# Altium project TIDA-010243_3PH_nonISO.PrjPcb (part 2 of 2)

## Sheet TIDA-010243_Hardware.SchDoc
size 431 x 279 mm; Date: Not shown in title block; ApprovedBy: Not shown in title block; CheckedBy: Not shown in title block; Author: Not shown in title block; CompanyName: Not shown in title block; Engineer: Not shown in title block; Organization: Not shown in title block; Address1: Not shown in title block; Address2: Not shown in title block; Address3: Not shown in title block; Address4: Not shown in title block; DocumentNumber: 3; Revision: Use project parameter SCH_Rev; SheetNumber: 4; SheetTotal: 4; PageSetup: Record=PageOptions¦CenterHorizontal=True¦CenterVertical=True¦PrintScale=1.00¦XCorrection=1.00¦YCorrection=1.00¦PrintKind=0¦BorderSize=5000000¦LeftOffset=0¦BottomOffset=0¦Orientation=2¦PaperLength=1000¦PaperWidth=1000¦Scale=100¦PaperSource=15¦PrintQuality=600¦MediaType=1¦DitherType=10¦PaperKind=Letter¦PrintScaleMode=1
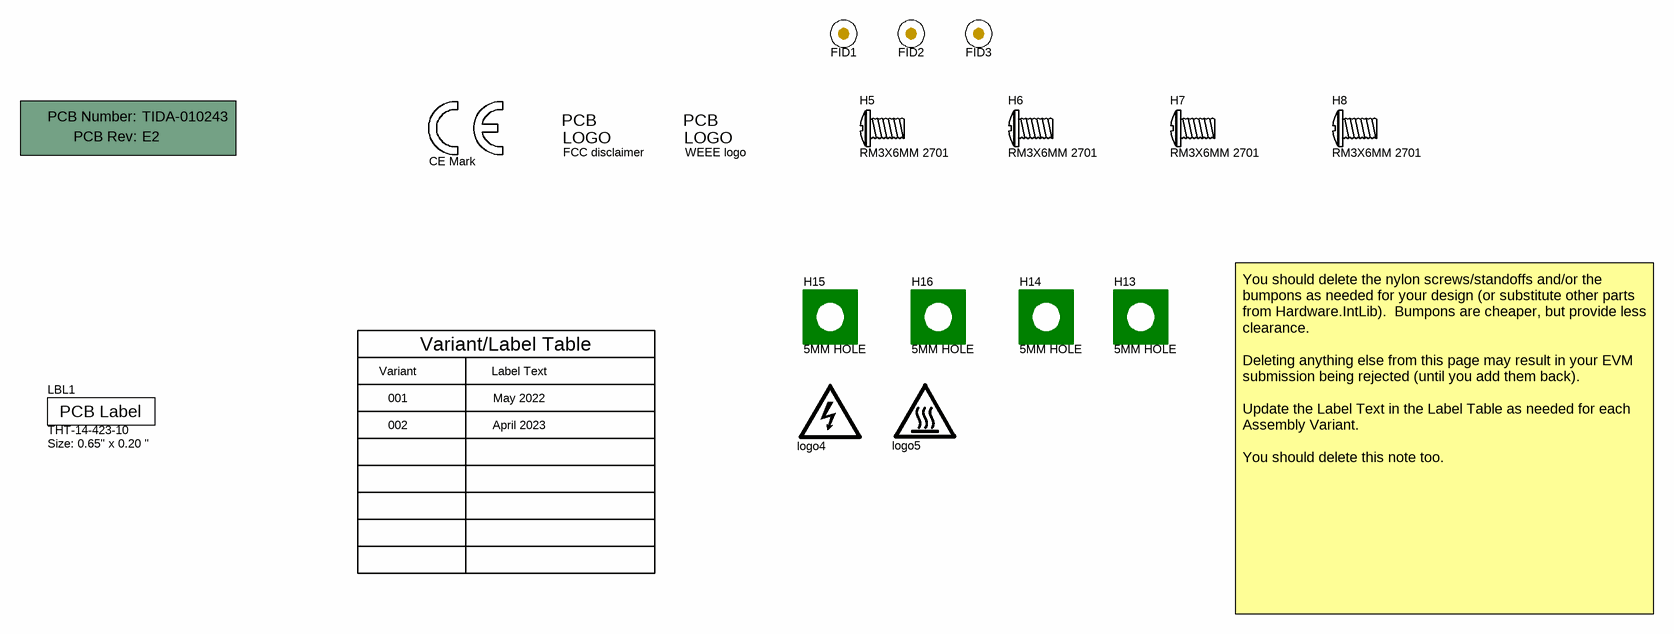
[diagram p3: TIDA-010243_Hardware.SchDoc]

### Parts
(Parts that share a designator on the sheet are numbered #1, #2 ... from top to bottom, then left to right.)
!PCB  Printed Circuit Board  (value not drawn)  (mechanical)
FID1  Fiducial  [Fiducial10-30]  (value not drawn)
FID2  Fiducial  [Fiducial10-30]  (value not drawn)
FID3  Fiducial  [Fiducial10-30]  (value not drawn)
H5  RM3X6MM 2701  (mechanical)
H6  RM3X6MM 2701  (mechanical)
H7  RM3X6MM 2701  (mechanical)
H8  RM3X6MM 2701  (mechanical)
H13  5MM HOLE  [5MM_HOLE]
H14  5MM HOLE  [5MM_HOLE]
H15  5MM HOLE  [5MM_HOLE]
H16  5MM HOLE  [5MM_HOLE]
LBL1  THT-14-423-10  Note: Size: 0.65" x 0.20 "  [Label_650x200]
Logo2  CE Mark  [CE_Mark_5mm]  (no BOM)
Logo3  FCC disclaimer  [FCC_disclaimer]  (no BOM)
Logo4#1  WEEE logo  [WEEE_Minimum]  (no BOM)
logo4#2  DANGER HIGH VOLTAGE  [IEC_HighVoltage_Large]  (value not drawn)  (no BOM)
logo5  CAUTION HOT SURFACE  [IEC_HotSurface_Large]  (value not drawn)  (no BOM)

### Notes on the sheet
- Variant
- Variant/Label Table
- Label Text
- 001
- 002
- May 2022
- April 2023
- You should delete the nylon screws/standoffs and/or the bumpons as needed for your design (or substitute other parts from Hardware.IntLib).  Bumpons are cheaper, but provide less clearance.
  Deleting anything else from this page may result in your EVM submission being rejected (until you add them back).
  Update the Label Text in the Label Table as needed for each Assembly Variant.
  You should delete this note too.

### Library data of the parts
!PCB = CMP-0003618-2: Manufacturer: Any; PartNumber: TIDA-010243
FID1-FID3 = CMP-0077181-1: Fiducial mark.  There is nothing to buy or mount.
H5-H8 = CMP-0077936-1: MACHINE SCREW PAN PHILLIPS M3; Manufacturer: APM HEXSEAL; CompType: Standoff
H13-H16 = CMP-0079337-1: 5 mm PCB Hole; Manufacturer: Any; CompType: Pad
LBL1 = CMP-0003625-1: Thermal Transfer Printable Labels, 0.650" W x 0.200" H - 10,000 per roll; Manufacturer: Brady; CompType: Label
Logo2 = CMP-0074844-1: SymbolCreator: a0412235
Logo3 = CMP-0074847-1: FCC_disclaimer; Library Reference: Logo
Logo4#1 = CMP-0074769-1
logo4#2 = CMP-0074835-1: IEC 61010-1 High Voltage Warning; SymbolCreator: a0412235
logo5 = CMP-0074837-2: IEC 61010-1 Hot Surface Warning; Manufacturer: Texas Instruments; SymbolCreator: a0412235; CompType: IC; AEC Category: Q200

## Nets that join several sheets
GND: TIDA_010243-MCU (32 pins), TIDA-010243-AFE (48 pins), TIDA-010243_Interfaces (11 pins)
VCC_EXTERN: TIDA_010243-MCU (16 pins), TIDA-010243-AFE (12 pins), TIDA-010243_Interfaces (9 pins)
ACT: TIDA_010243-MCU (D1.2 J7.1 U2.35), TIDA-010243_Interfaces (J13.3 U8.2)
ADS_CS: TIDA_010243-MCU (U2.58), TIDA-010243-AFE (R29.2 R59.1)
ADS_DIN_MSP_DOUT: TIDA_010243-MCU (U2.60), TIDA-010243-AFE (R18.2)
ADS_DOUT_MSP_DIN: TIDA_010243-MCU (U2.59), TIDA-010243-AFE (R20.2)
ADS_DRDY: TIDA_010243-MCU (U2.28), TIDA-010243-AFE (R23.2 R58.2)
ADS_SYNC_RESET: TIDA_010243-MCU (U2.29), TIDA-010243-AFE (R30.2 R61.1)
CTS_FTDI: TIDA_010243-MCU (U2.37), TIDA-010243_Interfaces (J10.2)
EM_RX_SECC_TX_UART: TIDA_010243-MCU (U2.57), TIDA-010243_Interfaces (J13.4)
EM_SECC_GPIO_UART: TIDA_010243-MCU (U2.5), TIDA-010243_Interfaces (J13.6)
EM_TX_SECC_RX_UART: TIDA_010243-MCU (U2.56), TIDA-010243_Interfaces (J13.2)
M0_CLKOUT: TIDA_010243-MCU (U2.18), TIDA-010243-AFE (R15.2)
M0_EN_from_SECC: TIDA_010243-MCU (U2.6), TIDA-010243_Interfaces (J13.7)
M0_GPIO1_SECC: TIDA_010243-MCU (U2.30), TIDA-010243_Interfaces (J13.9)
REACT: TIDA_010243-MCU (D2.2 J8.1 U2.39), TIDA-010243_Interfaces (J13.5 U8.3)
RTS_FTDI: TIDA_010243-MCU (U2.36), TIDA-010243_Interfaces (J10.6)
RXD_FTDI: TIDA_010243-MCU (U2.25), TIDA-010243_Interfaces (J10.5)
Serial_RE_DE: TIDA_010243-MCU (U2.64), TIDA-010243_Interfaces (U5.3)
Serial_RX: TIDA_010243-MCU (U2.55), TIDA-010243_Interfaces (U5.5)
Serial_TX: TIDA_010243-MCU (U2.54), TIDA-010243_Interfaces (U5.4)
SPI_SCK: TIDA_010243-MCU (U2.61), TIDA-010243-AFE (R22.2)
TMAG_INT: TIDA_010243-MCU (U2.31), TIDA-010243-AFE (R111.1 U9.5)
TMAG_SCL: TIDA_010243-MCU (U2.51), TIDA-010243-AFE (R109.1 U9.1)
TMAG_SDA: TIDA_010243-MCU (U2.50), TIDA-010243-AFE (R110.1 U9.6)
TXD_FTDI: TIDA_010243-MCU (U2.24), TIDA-010243_Interfaces (J10.4)

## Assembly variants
001: not fitted C52 C53 C54 C55 C56 C57 C58 C59 C60 C? FID1 FID2 FID3 J16 J17 J18 LCD1 R65 R66 R67 R? R? R? R? R? S3 S4 U10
